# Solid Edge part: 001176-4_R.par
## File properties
Last saved by: morva
Revision: 82
Accuracy: 0.990
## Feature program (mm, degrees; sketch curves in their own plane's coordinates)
body "unnamed Body 1"
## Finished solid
Body 1: solid body, 14 faces, 28 edges, 18 vertices.
  Faces by surface: cylinder 6, plane 4, torus 4
  Edges by curve: circle 19, line 6, spline 3
Bounding box of the edges (mm; curved faces can reach further): 7.324 x 11.596 x 8.434, from (428.2898, 370.5905, 172.9416) to (435.6133, 382.1866, 181.3752).
Cylindrical faces by radius (mm): R0.75 x2, R1.5 x2, R2.5 x2
Toroidal faces (ring radius, tube radius in mm): R1.125 r0.375 x2, R1.125 r1.5156 x2
Planar faces by outward normal: oblique 4
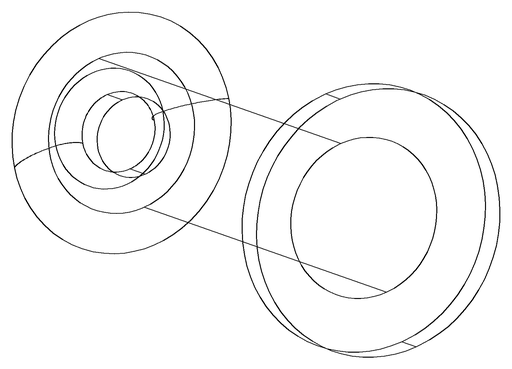
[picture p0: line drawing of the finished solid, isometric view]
